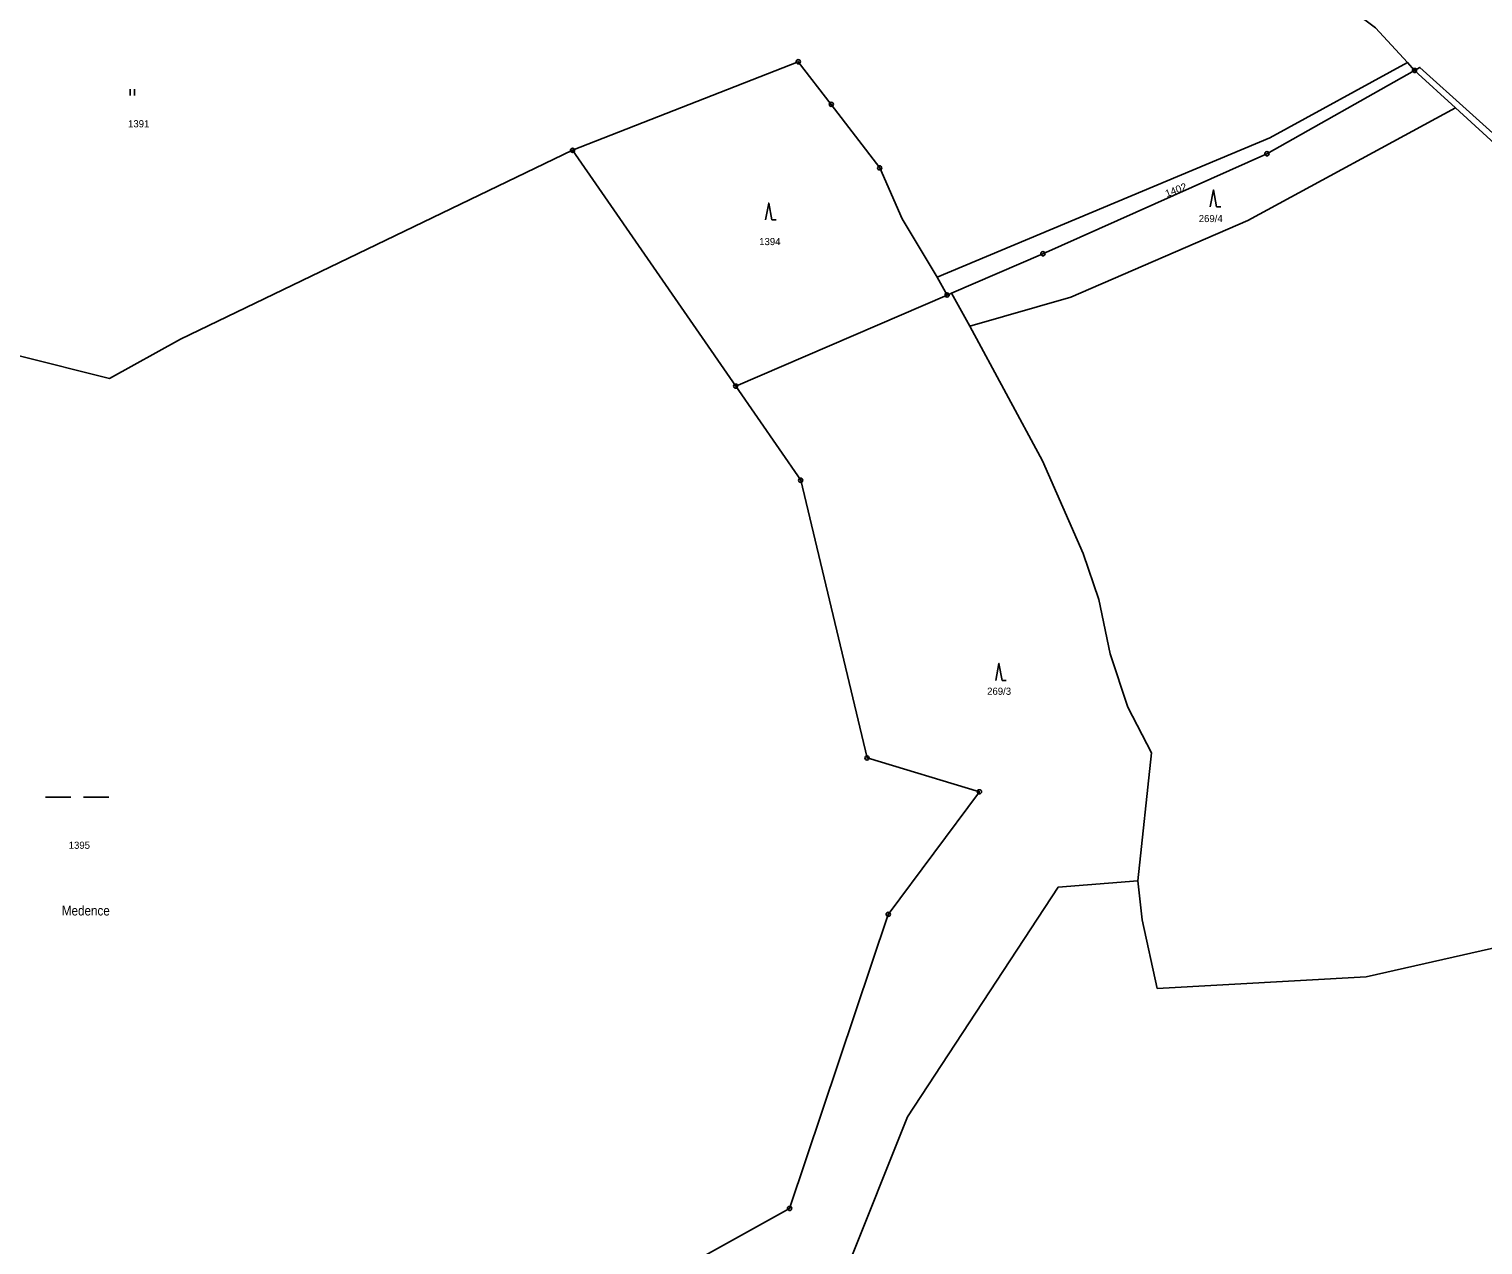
# Model space of a CAD drawing. Extents: x -872229 to -869198, y -1075981 to -1074329.
# Drawn here: x -870040 to -869694.9, y -1074938.2 to -1074649.5 of the extents above; entities that cross this region are included whole.
import ezdxf

# ---------------------------------------------------------------- set-up
doc = ezdxf.new("R2010")
doc.units = 0
doc.header["$LTSCALE"] = 0.68
for name, color, linetype, lineweight in [('1', 7, 'Continuous', 25), ('3', 7, 'Continuous', 25), ('7', 7, 'Continuous', 13), ('8', 7, 'Continuous', 25)]:
    doc.layers.add(name, color=color, linetype=linetype, lineweight=lineweight)
doc.layers.add('2', color=7, linetype='Continuous')

msp = doc.modelspace()

# ---------------------------------------------------------------- linework, layer by layer
at = {"layer": '1'}
for p, q in [((-869711.15, -1074659.32), (-869712.84, -1074657.47)), ((-869711.15, -1074659.32), (-869701.44, -1074668.21)), ((-869822.1, -1074712.65), (-869821.07, -1074712.21)), ((-869816.71, -1074720.02), (-869821.07, -1074712.21))]:
    msp.add_line(p, q, dxfattribs=at)
for points in [[(-869712.84, -1074657.47), (-869720.42, -1074649.17), (-869729.76, -1074642.12), (-869739.64, -1074635.61), (-869753.88, -1074626.92), (-869770.54, -1074620.9), (-869785.96, -1074613.96), (-869793.12, -1074610.67)], [(-869911.02, -1074678.28), (-869857.44, -1074657.25), (-869849.59, -1074667.37), (-869838.11, -1074682.45), (-869832.76, -1074694.54), (-869824.49, -1074708.42)], [(-869824.49, -1074708.42), (-869745.46, -1074675.33), (-869712.84, -1074657.47)], [(-869821.07, -1074712.21), (-869799.36, -1074702.85), (-869746.19, -1074679.1), (-869711.15, -1074659.32)], [(-869453.23, -1074793.29), (-869497.35, -1074770.43), (-869502.91, -1074766.99), (-869516.66, -1074755.78), (-869542.23, -1074736.35), (-869569.01, -1074723.84), (-869589.32, -1074714.31), (-869627.88, -1074704.89), (-869644.84, -1074704.23), (-869686.29, -1074679.82), (-869709.86, -1074658.59), (-869711.15, -1074659.32)], [(-869701.44, -1074668.21), (-869750.73, -1074694.98), (-869792.75, -1074713.16), (-869816.71, -1074720.02)], [(-869453.66, -1074794.85), (-869498.36, -1074771.77), (-869503.98, -1074768.2), (-869517.76, -1074757.22), (-869525.6, -1074751.31), (-869543.02, -1074738.02), (-869569.82, -1074725.31), (-869590.03, -1074715.95), (-869627.87, -1074706.45), (-869644.88, -1074705.89), (-869687.49, -1074680.97), (-869701.44, -1074668.21)], [(-870044.43, -1074699.07), (-870042.4, -1074727.1), (-870020.9, -1074732.51), (-870004.05, -1074723.11), (-869911.02, -1074678.28)], [(-869911.02, -1074678.28), (-869904.1, -1074688.29), (-869872.29, -1074734.28), (-869822.1, -1074712.65), (-869824.49, -1074708.42)], [(-869816.71, -1074720.02), (-869799.47, -1074751.99), (-869789.82, -1074774.02), (-869786.11, -1074784.95), (-869783.39, -1074797.89), (-869779.19, -1074810.5), (-869773.55, -1074821.33), (-869776.86, -1074851.73)], [(-869929.31, -1074968.38), (-869859.5, -1074929.56), (-869836.07, -1074859.72), (-869814.43, -1074830.62), (-869841.11, -1074822.59), (-869856.86, -1074756.63), (-869872.29, -1074734.28)], [(-869397.27, -1074865.36), (-869448.98, -1074844.13), (-869486.01, -1074834.03), (-869531.78, -1074827.54), (-869564.41, -1074831.36), (-869550.14, -1074861.73), (-869603.53, -1074857.64), (-869652.94, -1074860.42), (-869683.77, -1074865.74), (-869722.65, -1074874.59), (-869772.21, -1074877.32), (-869775.77, -1074861.05), (-869776.86, -1074851.73)], [(-869776.86, -1074851.73), (-869795.77, -1074853.27), (-869831.49, -1074907.84), (-869845.83, -1074943.67), (-869929.31, -1074968.38)]]:
    msp.add_lwpolyline(points, dxfattribs=at)
at = {"layer": '3'}
for p, q in [((-870016.021, -1074665.24), (-870016.021, -1074663.74)), ((-870015.02, -1074665.24), (-870015.02, -1074663.74)), ((-869758.12, -1074691.67), (-869757.124, -1074691.67)), ((-869863.69, -1074694.81), (-869862.694, -1074694.81)), ((-869809.05, -1074804.15), (-869808.054, -1074804.15)), ((-870036.119, -1074831.92), (-870030.119, -1074831.92)), ((-870027.119, -1074831.92), (-870021.119, -1074831.92))]:
    msp.add_line(p, q, dxfattribs=at)
for points in [[(-869863.69, -1074694.81), (-869864.44, -1074690.81), (-869865.19, -1074694.81)], [(-869758.12, -1074691.67), (-869758.87, -1074687.67), (-869759.62, -1074691.67)], [(-869809.05, -1074804.15), (-869809.8, -1074800.15), (-869810.55, -1074804.15)]]:
    msp.add_lwpolyline(points, dxfattribs=at)
at = {"layer": '8'}
for centre, radius in [((-869857.44, -1074657.2499), 0.5), ((-869857.44, -1074657.2499), 0.0303), ((-869711.15, -1074659.3199), 0.5), ((-869711.15, -1074659.3199), 0.0303), ((-869849.59, -1074667.3699), 0.5), ((-869849.59, -1074667.3699), 0.0303), ((-869911.02, -1074678.2799), 0.5), ((-869911.02, -1074678.2799), 0.0303), ((-869746.19, -1074679.0999), 0.5), ((-869746.19, -1074679.0999), 0.0303), ((-869838.11, -1074682.4499), 0.5), ((-869838.11, -1074682.4499), 0.0303), ((-869799.36, -1074702.8499), 0.5), ((-869799.36, -1074702.8499), 0.0303), ((-869822.1, -1074712.6499), 0.5), ((-869822.1, -1074712.6499), 0.0303), ((-869872.29, -1074734.2799), 0.5), ((-869872.29, -1074734.2799), 0.0303), ((-869856.86, -1074756.6299), 0.5), ((-869856.86, -1074756.6299), 0.0303), ((-869841.11, -1074822.5899), 0.5), ((-869841.11, -1074822.5899), 0.0303), ((-869814.43, -1074830.6199), 0.5), ((-869814.43, -1074830.6199), 0.0303), ((-869836.07, -1074859.7199), 0.5), ((-869836.07, -1074859.7199), 0.0303), ((-869859.5, -1074929.5599), 0.5), ((-869859.5, -1074929.5599), 0.0303)]:
    msp.add_circle(centre, radius, dxfattribs=at)

# ---------------------------------------------------------------- texts
at = {"layer": '2'}
for s, p in [('1391', (-870016.53, -1074672.83)), ('269/4', (-869762.37, -1074695.33)), ('1394', (-869866.71, -1074700.8)), ('269/3', (-869812.6, -1074807.59)), ('1395', (-870030.62, -1074844.16))]:
    msp.add_text(s, height=1.7, dxfattribs=at).set_placement(p)
at = {"layer": '2', "width": 1.05}
msp.add_text('1402', height=1.7, rotation=21, dxfattribs=at).set_placement((-869769.965, -1074689.443))
at = {"layer": '7', "width": 0.9}
msp.add_text('Medence', height=2.3, dxfattribs=at).set_placement((-870032.25, -1074859.99))

doc.saveas('drawing.dxf')
